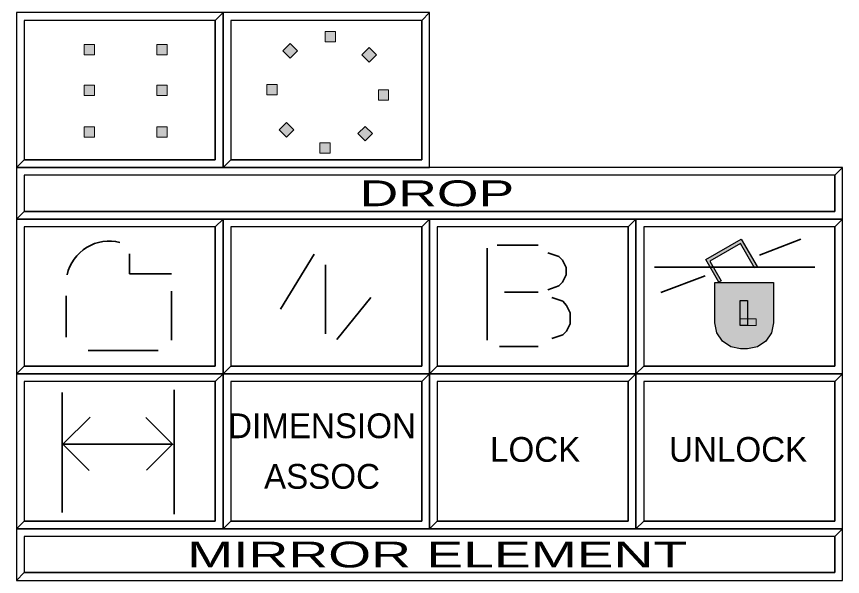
# Model space of a CAD drawing. Extents: x 95906.8 to 95923.6, y 90964.8 to 90972.8.
# Drawn here: x 95912.632 to 95914.232, y 90966.169 to 90967.254 of the extents above; entities that cross this region are included whole.
import ezdxf
from ezdxf.enums import TextEntityAlignment as Align

# ---------------------------------------------------------------- set-up
doc = ezdxf.new("R2010")
doc.units = 0
doc.header["$LTSCALE"] = 0.019
for name, color, linetype, lineweight in [('1', 7, 'Continuous', 25), ('11', 7, 'Continuous', 25), ('12', 7, 'Continuous', 25), ('18', 7, 'Continuous', 25), ('2', 7, 'Continuous', 13), ('3', 7, 'Continuous', 25), ('6', 7, 'Continuous', 35), ('7', 7, 'Continuous', 35)]:
    doc.layers.add(name, color=color, linetype=linetype, lineweight=lineweight)

msp = doc.modelspace()

# ---------------------------------------------------------------- hatches: boundary and pattern name
at = {"layer": '6'}
for points in [[(95913.2305, 90967.2054), (95913.2505, 90967.2054), (95913.2505, 90967.2254), (95913.2305, 90967.2254)], [(95912.7636, 90967.1801), (95912.7836, 90967.1801), (95912.7836, 90967.2001), (95912.7636, 90967.2001)], [(95912.9043, 90967.1801), (95912.9243, 90967.1801), (95912.9243, 90967.2001), (95912.9043, 90967.2001)], [(95913.1626, 90967.1734), (95913.1767, 90967.1875), (95913.1626, 90967.2017), (95913.1485, 90967.1875)], [(95913.3012, 90967.18), (95913.3153, 90967.1659), (95913.3295, 90967.18), (95913.3153, 90967.1941)], [(95912.7636, 90967.101), (95912.7836, 90967.101), (95912.7836, 90967.121), (95912.7636, 90967.121)], [(95912.9043, 90967.101), (95912.9243, 90967.101), (95912.9243, 90967.121), (95912.9043, 90967.121)], [(95913.1372, 90967.1027), (95913.1372, 90967.1227), (95913.1172, 90967.1227), (95913.1172, 90967.1027)], [(95913.3332, 90967.1121), (95913.3332, 90967.0921), (95913.3532, 90967.0921), (95913.3532, 90967.1121)], [(95912.7636, 90967.0204), (95912.7836, 90967.0204), (95912.7836, 90967.0404), (95912.7636, 90967.0404)], [(95912.9043, 90967.0204), (95912.9243, 90967.0204), (95912.9243, 90967.0404), (95912.9043, 90967.0404)], [(95913.1692, 90967.0348), (95913.1551, 90967.0489), (95913.1409, 90967.0348), (95913.1551, 90967.0207)], [(95913.3078, 90967.0414), (95913.2937, 90967.0273), (95913.3078, 90967.0131), (95913.3219, 90967.0273)], [(95913.2399, 90967.0094), (95913.2199, 90967.0094), (95913.2199, 90966.9894), (95913.2399, 90966.9894)], [(95913.9928, 90966.7395), (95913.9675, 90966.7833), (95914.0361, 90966.8229), (95914.0668, 90966.7698), (95914.0621, 90966.7671), (95914.0349, 90966.8145), (95913.9753, 90966.7803), (95913.9973, 90966.7421)], [(95913.985, 90966.6604), (95913.985, 90966.7388), (95914.0985, 90966.7388), (95914.0985, 90966.6604), (95914.0947, 90966.6413), (95914.0839, 90966.625), (95914.0676, 90966.6142), (95914.0485, 90966.6104), (95914.035, 90966.6104), (95914.0159, 90966.6142), (95913.9996, 90966.625), (95913.9888, 90966.6413)], [(95914.034, 90966.7039), (95914.0482, 90966.7039), (95914.0482, 90966.6558), (95914.034, 90966.6558)], [(95914.034, 90966.6558), (95914.0653, 90966.6558), (95914.0653, 90966.6683), (95914.034, 90966.6683)]]:
    msp.add_hatch(color=256, dxfattribs=at).paths.add_polyline_path(points)

# ---------------------------------------------------------------- linework, layer by layer
at = {"layer": '1'}
for points in [[(95912.6323, 90966.9617), (95913.0323, 90966.9617), (95913.0323, 90967.2617), (95912.6323, 90967.2617)], [(95913.0323, 90966.9617), (95913.4323, 90966.9617), (95913.4323, 90967.2617), (95913.0323, 90967.2617)], [(95912.6323, 90966.8617), (95914.2323, 90966.8617), (95914.2323, 90966.9617), (95912.6323, 90966.9617)], [(95912.6323, 90966.5617), (95913.0323, 90966.5617), (95913.0323, 90966.8617), (95912.6323, 90966.8617)], [(95913.0323, 90966.5617), (95913.4323, 90966.5617), (95913.4323, 90966.8617), (95913.0323, 90966.8617)], [(95913.4323, 90966.5617), (95913.8323, 90966.5617), (95913.8323, 90966.8617), (95913.4323, 90966.8617)], [(95913.8323, 90966.5617), (95914.2323, 90966.5617), (95914.2323, 90966.8617), (95913.8323, 90966.8617)], [(95912.6323, 90966.2617), (95913.0323, 90966.2617), (95913.0323, 90966.5617), (95912.6323, 90966.5617)], [(95913.0323, 90966.2617), (95913.4323, 90966.2617), (95913.4323, 90966.5617), (95913.0323, 90966.5617)], [(95913.4323, 90966.2617), (95913.8323, 90966.2617), (95913.8323, 90966.5617), (95913.4323, 90966.5617)], [(95913.8323, 90966.2617), (95914.2323, 90966.2617), (95914.2323, 90966.5617), (95913.8323, 90966.5617)], [(95912.6323, 90966.1617), (95914.2323, 90966.1617), (95914.2323, 90966.2617), (95912.6323, 90966.2617)]]:
    msp.add_lwpolyline(points, close=True, dxfattribs=at)
at = {"layer": '11'}
for points in [[(95912.6473, 90966.9767), (95913.0173, 90966.9767), (95913.0173, 90967.2467), (95912.6473, 90967.2467)], [(95913.0473, 90966.9767), (95913.4173, 90966.9767), (95913.4173, 90967.2467), (95913.0473, 90967.2467)], [(95913.0473, 90966.5767), (95913.4173, 90966.5767), (95913.4173, 90966.8467), (95913.0473, 90966.8467)], [(95913.4473, 90966.5767), (95913.8173, 90966.5767), (95913.8173, 90966.8467), (95913.4473, 90966.8467)], [(95913.8473, 90966.5767), (95914.2173, 90966.5767), (95914.2173, 90966.8467), (95913.8473, 90966.8467)], [(95912.6473, 90966.2767), (95913.0173, 90966.2767), (95913.0173, 90966.5467), (95912.6473, 90966.5467)], [(95913.0473, 90966.2767), (95913.4173, 90966.2767), (95913.4173, 90966.5467), (95913.0473, 90966.5467)], [(95913.4473, 90966.2767), (95913.8173, 90966.2767), (95913.8173, 90966.5467), (95913.4473, 90966.5467)], [(95913.8473, 90966.2767), (95914.2173, 90966.2767), (95914.2173, 90966.5467), (95913.8473, 90966.5467)]]:
    msp.add_lwpolyline(points, close=True, dxfattribs=at)
at = {"layer": '12'}
msp.add_lwpolyline([(95912.6473, 90966.5767), (95913.0173, 90966.5767), (95913.0173, 90966.8467), (95912.6473, 90966.8467)], close=True, dxfattribs=at)
at = {"layer": '18'}
for points in [[(95912.6473, 90966.8767), (95914.2173, 90966.8767), (95914.2173, 90966.9467), (95912.6473, 90966.9467)], [(95912.6473, 90966.1767), (95914.2173, 90966.1767), (95914.2173, 90966.2467), (95912.6473, 90966.2467)]]:
    msp.add_lwpolyline(points, close=True, dxfattribs=at)
at = {"layer": '2'}
for points in [[(95912.6323, 90967.2617), (95912.6323, 90966.9617), (95912.6473, 90966.9767), (95912.6473, 90967.2467), (95913.0173, 90967.2467), (95913.0323, 90967.2617)], [(95913.0323, 90967.2617), (95913.0323, 90966.9617), (95913.0473, 90966.9767), (95913.0473, 90967.2467), (95913.4173, 90967.2467), (95913.4323, 90967.2617)], [(95912.6323, 90966.9617), (95912.6323, 90966.8617), (95912.6473, 90966.8767), (95912.6473, 90966.9467), (95914.2173, 90966.9467), (95914.2323, 90966.9617)], [(95912.6323, 90966.8617), (95912.6323, 90966.5617), (95912.6473, 90966.5767), (95912.6473, 90966.8467), (95913.0173, 90966.8467), (95913.0323, 90966.8617)], [(95913.0323, 90966.8617), (95913.0323, 90966.5617), (95913.0473, 90966.5767), (95913.0473, 90966.8467), (95913.4173, 90966.8467), (95913.4323, 90966.8617)], [(95913.4323, 90966.8617), (95913.4323, 90966.5617), (95913.4473, 90966.5767), (95913.4473, 90966.8467), (95913.8173, 90966.8467), (95913.8323, 90966.8617)], [(95913.8323, 90966.8617), (95913.8323, 90966.5617), (95913.8473, 90966.5767), (95913.8473, 90966.8467), (95914.2173, 90966.8467), (95914.2323, 90966.8617)], [(95912.6323, 90966.5617), (95912.6323, 90966.2617), (95912.6473, 90966.2767), (95912.6473, 90966.5467), (95913.0173, 90966.5467), (95913.0323, 90966.5617)], [(95913.0323, 90966.5617), (95913.0323, 90966.2617), (95913.0473, 90966.2767), (95913.0473, 90966.5467), (95913.4173, 90966.5467), (95913.4323, 90966.5617)], [(95913.4323, 90966.5617), (95913.4323, 90966.2617), (95913.4473, 90966.2767), (95913.4473, 90966.5467), (95913.8173, 90966.5467), (95913.8323, 90966.5617)], [(95913.8323, 90966.5617), (95913.8323, 90966.2617), (95913.8473, 90966.2767), (95913.8473, 90966.5467), (95914.2173, 90966.5467), (95914.2323, 90966.5617)], [(95912.6323, 90966.2617), (95912.6323, 90966.1617), (95912.6473, 90966.1767), (95912.6473, 90966.2467), (95914.2173, 90966.2467), (95914.2323, 90966.2617)]]:
    msp.add_lwpolyline(points, close=True, dxfattribs=at)
at = {"layer": '3'}
for points in [[(95912.6323, 90966.9617), (95913.0323, 90966.9617), (95913.0323, 90967.2617), (95913.0173, 90967.2467), (95913.0173, 90966.9767), (95912.6473, 90966.9767)], [(95913.0323, 90966.9617), (95913.4323, 90966.9617), (95913.4323, 90967.2617), (95913.4173, 90967.2467), (95913.4173, 90966.9767), (95913.0473, 90966.9767)], [(95912.6323, 90966.8617), (95914.2323, 90966.8617), (95914.2323, 90966.9617), (95914.2173, 90966.9467), (95914.2173, 90966.8767), (95912.6473, 90966.8767)], [(95912.6323, 90966.5617), (95913.0323, 90966.5617), (95913.0323, 90966.8617), (95913.0173, 90966.8467), (95913.0173, 90966.5767), (95912.6473, 90966.5767)], [(95913.0323, 90966.5617), (95913.4323, 90966.5617), (95913.4323, 90966.8617), (95913.4173, 90966.8467), (95913.4173, 90966.5767), (95913.0473, 90966.5767)], [(95913.4323, 90966.5617), (95913.8323, 90966.5617), (95913.8323, 90966.8617), (95913.8173, 90966.8467), (95913.8173, 90966.5767), (95913.4473, 90966.5767)], [(95913.8323, 90966.5617), (95914.2323, 90966.5617), (95914.2323, 90966.8617), (95914.2173, 90966.8467), (95914.2173, 90966.5767), (95913.8473, 90966.5767)], [(95912.6323, 90966.2617), (95913.0323, 90966.2617), (95913.0323, 90966.5617), (95913.0173, 90966.5467), (95913.0173, 90966.2767), (95912.6473, 90966.2767)], [(95913.0323, 90966.2617), (95913.4323, 90966.2617), (95913.4323, 90966.5617), (95913.4173, 90966.5467), (95913.4173, 90966.2767), (95913.0473, 90966.2767)], [(95913.4323, 90966.2617), (95913.8323, 90966.2617), (95913.8323, 90966.5617), (95913.8173, 90966.5467), (95913.8173, 90966.2767), (95913.4473, 90966.2767)], [(95913.8323, 90966.2617), (95914.2323, 90966.2617), (95914.2323, 90966.5617), (95914.2173, 90966.5467), (95914.2173, 90966.2767), (95913.8473, 90966.2767)], [(95912.6323, 90966.1617), (95914.2323, 90966.1617), (95914.2323, 90966.2617), (95914.2173, 90966.2467), (95914.2173, 90966.1767), (95912.6473, 90966.1767)]]:
    msp.add_lwpolyline(points, close=True, dxfattribs=at)
at = {"layer": '6'}
for p, q in [((95914.1519, 90966.8228), (95914.0715, 90966.7921)), ((95913.5441, 90966.8053), (95913.5441, 90966.6271)), ((95913.5631, 90966.8114), (95913.643, 90966.8114)), ((95913.1434, 90966.687), (95913.2087, 90966.7935)), ((95913.231, 90966.6393), (95913.231, 90966.773)), ((95913.8683, 90966.7685), (95914.179, 90966.7685)), ((95913.8802, 90966.7192), (95913.966, 90966.7519)), ((95912.9328, 90966.7223), (95912.9328, 90966.627)), ((95913.5779, 90966.7203), (95913.643, 90966.7203)), ((95912.7284, 90966.6332), (95912.7284, 90966.7131)), ((95913.3186, 90966.71), (95913.2531, 90966.6284)), ((95913.643, 90966.6149), (95913.5677, 90966.6149)), ((95912.9067, 90966.6071), (95912.7714, 90966.6071)), ((95912.9379, 90966.5308), (95912.9379, 90966.2897)), ((95912.7206, 90966.5257), (95912.7206, 90966.2931)), ((95912.7223, 90966.4255), (95912.7747, 90966.4779)), ((95912.7223, 90966.4255), (95912.773, 90966.3747)), ((95912.9345, 90966.4255), (95912.8842, 90966.3752))]:
    msp.add_line(p, q, dxfattribs=at)
at = {"layer": '6', "lineweight": 13}
for points in [[(95913.2305, 90967.2054), (95913.2505, 90967.2054), (95913.2505, 90967.2254), (95913.2305, 90967.2254)], [(95912.7636, 90967.1801), (95912.7836, 90967.1801), (95912.7836, 90967.2001), (95912.7636, 90967.2001)], [(95912.9043, 90967.1801), (95912.9243, 90967.1801), (95912.9243, 90967.2001), (95912.9043, 90967.2001)], [(95913.1626, 90967.1734), (95913.1767, 90967.1875), (95913.1626, 90967.2017), (95913.1485, 90967.1875)], [(95913.3012, 90967.18), (95913.3153, 90967.1659), (95913.3295, 90967.18), (95913.3153, 90967.1941)], [(95912.7636, 90967.101), (95912.7836, 90967.101), (95912.7836, 90967.121), (95912.7636, 90967.121)], [(95912.9043, 90967.101), (95912.9243, 90967.101), (95912.9243, 90967.121), (95912.9043, 90967.121)], [(95913.1372, 90967.1027), (95913.1372, 90967.1227), (95913.1172, 90967.1227), (95913.1172, 90967.1027)], [(95913.3332, 90967.1121), (95913.3332, 90967.0921), (95913.3532, 90967.0921), (95913.3532, 90967.1121)], [(95912.7636, 90967.0204), (95912.7836, 90967.0204), (95912.7836, 90967.0404), (95912.7636, 90967.0404)], [(95912.9043, 90967.0204), (95912.9243, 90967.0204), (95912.9243, 90967.0404), (95912.9043, 90967.0404)], [(95913.1692, 90967.0348), (95913.1551, 90967.0489), (95913.1409, 90967.0348), (95913.1551, 90967.0207)], [(95913.3078, 90967.0414), (95913.2937, 90967.0273), (95913.3078, 90967.0131), (95913.3219, 90967.0273)], [(95913.2399, 90967.0094), (95913.2199, 90967.0094), (95913.2199, 90966.9894), (95913.2399, 90966.9894)], [(95914.034, 90966.6558), (95914.0653, 90966.6558), (95914.0653, 90966.6683), (95914.034, 90966.6683)]]:
    msp.add_lwpolyline(points, close=True, dxfattribs=at)
at = {"layer": '6', "lineweight": 25}
for points in [[(95913.9928, 90966.7395), (95913.9675, 90966.7833), (95914.0361, 90966.8229), (95914.0668, 90966.7698), (95914.0621, 90966.7671), (95914.0349, 90966.8145), (95913.9753, 90966.7803), (95913.9973, 90966.7421)], [(95913.985, 90966.6604), (95913.985, 90966.7388), (95914.0985, 90966.7388), (95914.0985, 90966.6604), (95914.0947, 90966.6413), (95914.0839, 90966.625), (95914.0676, 90966.6142), (95914.0485, 90966.6104), (95914.035, 90966.6104), (95914.0159, 90966.6142), (95913.9996, 90966.625), (95913.9888, 90966.6413)], [(95914.034, 90966.7039), (95914.0482, 90966.7039), (95914.0482, 90966.6558), (95914.034, 90966.6558)]]:
    msp.add_lwpolyline(points, close=True, dxfattribs=at)
at = {"layer": '6'}
for points in [[(95912.9328, 90966.7557), (95912.8513, 90966.7557), (95912.8513, 90966.7946)], [(95913.6614, 90966.796), (95913.6828, 90966.7889), (95913.6899, 90966.7818), (95913.697, 90966.7676), (95913.697, 90966.7534), (95913.6899, 90966.7392), (95913.6828, 90966.7321), (95913.6614, 90966.7249)], [(95913.6691, 90966.7095), (95913.6905, 90966.7024), (95913.6976, 90966.6941), (95913.7047, 90966.6799), (95913.7047, 90966.6586), (95913.6976, 90966.6444), (95913.6905, 90966.6373), (95913.6691, 90966.6302)], [(95912.7223, 90966.4255), (95912.9345, 90966.4255), (95912.883, 90966.477)]]:
    msp.add_lwpolyline(points, dxfattribs=at)
msp.add_arc((95912.8121, 90966.7354), 0.0838, 75.8303, 167.4043, dxfattribs=at)

# ---------------------------------------------------------------- texts
for s, p in [('DIMENSION', (95913.2241, 90966.4372)), ('LOCK', (95913.637, 90966.3914)), ('UNLOCK', (95914.0302, 90966.3914)), ('ASSOC', (95913.2241, 90966.3392))]:
    msp.add_text(s, height=0.048, dxfattribs=at).set_placement(p, align=Align.CENTER)
at = {"layer": '7'}
for s, width, p in [('          DROP         ', 1.55, (95913.4322, 90966.8867)), ('     MIRROR ELEMENT    ', 1.6, (95913.4322, 90966.1867))]:
    msp.add_text(s, height=0.04999, dxfattribs=dict(at, width=width)).set_placement(p, align=Align.CENTER)

doc.saveas('drawing.dxf')
